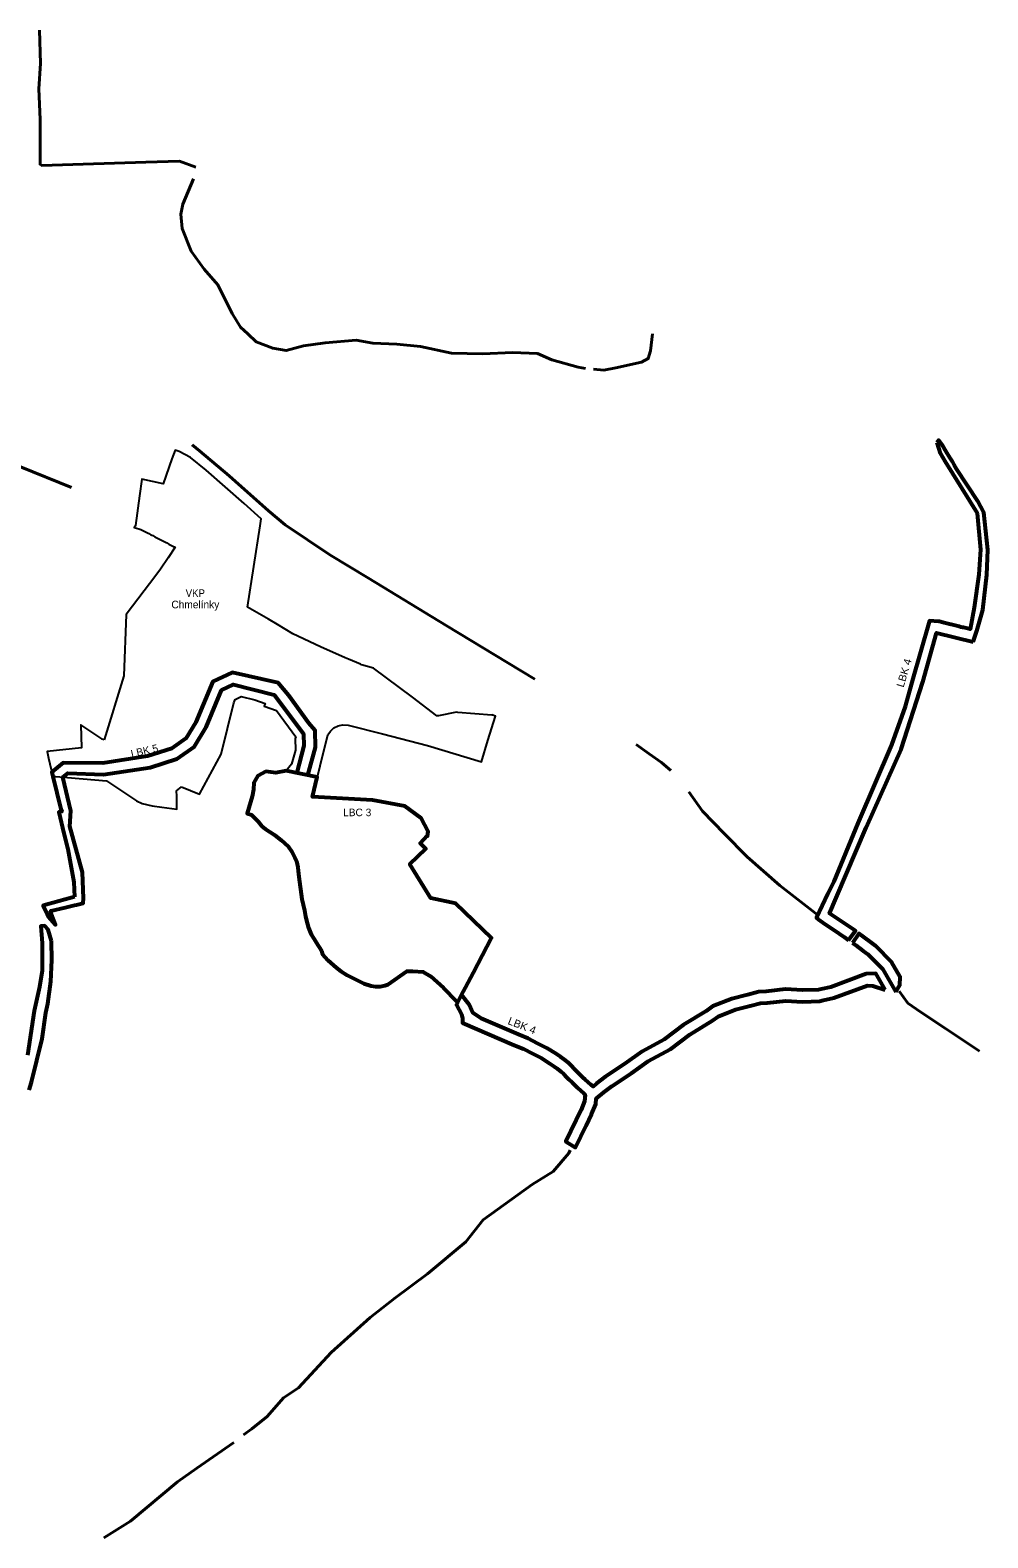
# Model space of a CAD drawing. Extents: x -555426 to -553015, y -1186745 to -1182687.
# Drawn here: x -554278 to -553015, y -1186745 to -1184759 of the extents above; entities that cross this region are included whole.
import ezdxf
from ezdxf.enums import TextEntityAlignment as Align

# ---------------------------------------------------------------- set-up
doc = ezdxf.new("R2010")
doc.units = 0
doc.header["$LTSCALE"] = 4
for name, color, linetype, lineweight in [('10', 7, 'Continuous', 25), ('12', 7, 'Continuous', 53), ('14', 7, 'Continuous', 53), ('51', 7, 'Continuous', 40)]:
    doc.layers.add(name, color=color, linetype=linetype, lineweight=lineweight)
doc.layers.add('13', color=7, linetype='Continuous')

msp = doc.modelspace()

# ---------------------------------------------------------------- linework, layer by layer
at = {"layer": '10'}
for points in [[(-553991.445, -1185519.302), (-553974.35, -1185411.9), (-553973.359, -1185402.641), (-553995.47, -1185382.52), (-554045.89, -1185338.45), (-554066.15, -1185321.95), (-554081.51, -1185313.86), (-554086.79, -1185312.33), (-554090.82, -1185323.71), (-554102.45, -1185356.48), (-554130.41, -1185350.705), (-554133.37, -1185372.6)], [(-554133.37, -1185372.6), (-554138.66, -1185411.73), (-554139.35, -1185412.26), (-554140.43, -1185414.36), (-554137.51, -1185415.07), (-554134.63, -1185415.78), (-554131.86, -1185416.61), (-554129.16, -1185417.97), (-554126.51, -1185419.33), (-554123.86, -1185420.72), (-554121.2, -1185422.09), (-554118.58, -1185423.63), (-554115.87, -1185424.86), (-554113.33, -1185426.32), (-554110.66, -1185427.61), (-554108, -1185428.97), (-554105.33, -1185430.33), (-554102.72, -1185431.7), (-554100.13, -1185433.15), (-554097.46, -1185434.4), (-554094.78, -1185435.91), (-554092.21, -1185437.3), (-554089.57, -1185438.64), (-554086.65, -1185440.17), (-554095.82, -1185454), (-554105.95, -1185469.05), (-554112.25, -1185477.32), (-554151.37, -1185528.59), (-554154.044, -1185609.726), (-554179.932, -1185693.741)], [(-553777.28, -1185857.816), (-553756.305, -1185837.627), (-553763.69, -1185830.09), (-553754.66, -1185819.8), (-553753.808, -1185820.661), (-553753.12, -1185814.47), (-553762.294, -1185797.04), (-553784.005, -1185781.139), (-553826.511, -1185773.188), (-553905.747, -1185768.755), (-553885.33, -1185687.443), (-553881.88, -1185682.283), (-553877.278, -1185678.216), (-553871.606, -1185675.434), (-553866.147, -1185674.256), (-553858.583, -1185674.394), (-553813.14, -1185685.807), (-553754.191, -1185701.479), (-553682.621, -1185722.715), (-553674.53, -1185694.64), (-553664.47, -1185662.51), (-553669.09, -1185660.85), (-553669.37, -1185661.4), (-553714.12, -1185657.64), (-553715.92, -1185657.49), (-553739.47, -1185662.06), (-553741.7, -1185662.44), (-553773.82, -1185637.86), (-553825.09, -1185599.26), (-553840.96, -1185594.97), (-553842.47, -1185594.31), (-553858.01, -1185587.49), (-553862.7, -1185585.67), (-553895.22, -1185571.18), (-553931.3, -1185554.25), (-553951.62, -1185541.91), (-553963.43, -1185534.75), (-553991.445, -1185519.302)], [(-554078.43, -1185755.55), (-554066.24, -1185760.67), (-554054.322, -1185765.455), (-554025.99, -1185712.685), (-554009.42, -1185645.24), (-554007.69, -1185640.76), (-553999.63, -1185636.97), (-553981.77, -1185641.17), (-553968.11, -1185645.82), (-553969.11, -1185649.61), (-553953.01, -1185655.12), (-553927.56, -1185690.05), (-553928.37, -1185692.13), (-553928.035, -1185707.442), (-553933.233, -1185725.789), (-553940.266, -1185734.657), (-553953.721, -1185737.409), (-553967.176, -1185735.575), (-553977.573, -1185741.079), (-553982.772, -1185750.559), (-553983.383, -1185759.121), (-553984.912, -1185768.295), (-553991.544, -1185790.708), (-553986.08, -1185792.84), (-553977.08, -1185801.46), (-553972.23, -1185807.6), (-553968.15, -1185811.02), (-553955.74, -1185819.21), (-553950.713, -1185822.993), (-553946.85, -1185825.9), (-553937.49, -1185834.57), (-553932.62, -1185841.17), (-553928.66, -1185848.69), (-553926.78, -1185853.53), (-553924.99, -1185861.78), (-553924.28, -1185866.6), (-553923.67, -1185874.2), (-553919.55, -1185903.59), (-553916.21, -1185918.48), (-553914.68, -1185926.61), (-553912.17, -1185936.62), (-553911.06, -1185941.63), (-553907.2, -1185950.33), (-553903.49, -1185956.33), (-553900.68, -1185960.74)], [(-554179.932, -1185693.741), (-554183.1, -1185693.05), (-554184.61, -1185691.85), (-554211.02, -1185674.13), (-554209.941, -1185704.245), (-554255.433, -1185709.182), (-554253.33, -1185718.22), (-554247.64, -1185742.08), (-554244.07, -1185742.37), (-554177.07, -1185747.73), (-554137.54, -1185774.16), (-554130.2, -1185777.76), (-554116.73, -1185780.93)], [(-554116.73, -1185780.93), (-554104.34, -1185782.34), (-554084.28, -1185785.25), (-554084.59, -1185768.1), (-554085.01, -1185761.01), (-554078.43, -1185755.55)], [(-553868.12, -1185998.62), (-553860.09, -1186003.76), (-553838.07, -1186014.61), (-553828.19, -1186017.87), (-553822.68, -1186018.8), (-553816.22, -1186018.59), (-553810.09, -1186017.51), (-553806.36, -1186016.14), (-553781.21, -1185998.52), (-553773.17, -1185998.47), (-553759.89, -1185999.41), (-553750.12, -1186005), (-553732.97, -1186020.51), (-553715.77, -1186037.98), (-553714.54, -1186040.11), (-553709.22, -1186029.91), (-553704, -1186019.94), (-553693.38, -1186000.29), (-553681.6, -1185977.59), (-553669.55, -1185954.79), (-553716.551, -1185909.351), (-553749.515, -1185902.394), (-553777.28, -1185857.816)], [(-553900.68, -1185960.74), (-553893.92, -1185971.59), (-553892.19, -1185976.11), (-553885.57, -1185984.25), (-553874.36, -1185993.93), (-553868.12, -1185998.62)]]:
    msp.add_lwpolyline(points, dxfattribs=at)
at = {"layer": '12'}
for points in [[(-553082.87, -1185302.3), (-553078.12, -1185316.33), (-553072.189, -1185326.659), (-553029.75, -1185395.3), (-553025.31, -1185442.94), (-553027.49, -1185476.25), (-553033.31, -1185519.72), (-553038.96, -1185548.27), (-553047.67, -1185546.08), (-553048.91, -1185545.77), (-553050.91, -1185545.27), (-553053.3, -1185544.68), (-553063.75, -1185542.07), (-553066.22, -1185541.44), (-553072.87, -1185539.73), (-553077.5, -1185538.57), (-553079.01, -1185538.14), (-553080.42, -1185537.9), (-553092.39, -1185537.23), (-553104.36, -1185578.25), (-553114.18, -1185613.7), (-553124.36, -1185649.89), (-553142.42, -1185700.66), (-553186.75, -1185803.57), (-553218.6, -1185880.58), (-553226.41, -1185896.66), (-553241.32, -1185928.48), (-553239.31, -1185930.03), (-553229.98, -1185936.55), (-553218.58, -1185944.24), (-553204.56, -1185953.8), (-553198.95, -1185957.78)], [(-553034.928, -1185564.727), (-553030.13, -1185550.39), (-553022.24, -1185522.46), (-553016.78, -1185476.64), (-553015.45, -1185443.7), (-553020.83, -1185394.62), (-553028.51, -1185379.69), (-553056.68, -1185336.83), (-553059.75, -1185331.58), (-553062.27, -1185327.43), (-553065.55, -1185322), (-553070.46, -1185313.92), (-553074.85, -1185306.8), (-553080.44, -1185299.18), (-553082.87, -1185302.3)], [(-553198.95, -1185957.78), (-553190.044, -1185945.316), (-553224.037, -1185922.537), (-553215.31, -1185901.96), (-553175.94, -1185809.23), (-553129.62, -1185706.16), (-553101.04, -1185617.53), (-553083.083, -1185552.819), (-553034.928, -1185564.727)], [(-553911.701, -1185740.404), (-553901.745, -1185703.425), (-553902.205, -1185681.771), (-553910.4, -1185671.8), (-553936.71, -1185635.55), (-553950.94, -1185618.77), (-554011.334, -1185605.071), (-554036.928, -1185617.149), (-554059.19, -1185670.456), (-554072.415, -1185692.214), (-554090.982, -1185705.416), (-554123.033, -1185715.514), (-554181.927, -1185724.575), (-554233.989, -1185724.118), (-554248.948, -1185736.596), (-554247.64, -1185742.08), (-554237.39, -1185785.09), (-554235.75, -1185788.44), (-554240.03, -1185789.13), (-554233.38, -1185817.23), (-554228.1, -1185837.77), (-554220.03, -1185881.16), (-554219.04, -1185900.71)], [(-554219.04, -1185900.71), (-554260.557, -1185912.173), (-554256.71, -1185920.61), (-554254.1, -1185926.61), (-554244.35, -1185937.42), (-554249.57, -1185923.77), (-554250.31, -1185919.09), (-554231.43, -1185914.6), (-554219.41, -1185911.75), (-554216.82, -1185911.13), (-554207.981, -1185909.04), (-554207.51, -1185902.62), (-554208.92, -1185868.43), (-554225.516, -1185808.235), (-554224.11, -1185787.364), (-554234.745, -1185743.116), (-554228.051, -1185737.626), (-554180.845, -1185739.585), (-554119.619, -1185730.166), (-554084.218, -1185719.012), (-554061.203, -1185702.646), (-554045.784, -1185677.28), (-554025.31, -1185628.253), (-554009.786, -1185620.927), (-553956.216, -1185634.769), (-553917.292, -1185685.82), (-553916.787, -1185701.599), (-553926.437, -1185737.439)], [(-554249.398, -1185958.956), (-554253.834, -1185943.99), (-554258.932, -1185938.814), (-554263.54, -1185939.09), (-554261.93, -1185961.69), (-554261.867, -1185997.814), (-554265.332, -1186019.412), (-554272.29, -1186050.65), (-554281.22, -1186109.23)], [(-554278.86, -1186154.79), (-554275.9, -1186144.9), (-554261.77, -1186087.91), (-554257.23, -1186053.46), (-554254.24, -1186041.58), (-554250.48, -1186012.28), (-554249.25, -1185984.3), (-554249.398, -1185958.956)], [(-553136.76, -1186025.81), (-553131.636, -1186017.15), (-553130.875, -1186005.959), (-553141.815, -1185986.942), (-553163.584, -1185965.017), (-553170.649, -1185959.736), (-553185.396, -1185948.905), (-553193.99, -1185961.2)], [(-553193.99, -1185961.2), (-553189.33, -1185964.5), (-553179.63, -1185971.75), (-553173.45, -1185976.37), (-553153.84, -1185996.12), (-553136.76, -1186025.81)], [(-553150.76, -1186023.24), (-553162.91, -1186001.77), (-553175.828, -1186001.958), (-553222.523, -1186019.488), (-553235.037, -1186022.23), (-553238.873, -1186023.052), (-553259.583, -1186023.736), (-553282.021, -1186022.434), (-553307.71, -1186025.165), (-553317.736, -1186025.993), (-553332.406, -1186029.69), (-553352.717, -1186034.988), (-553378.046, -1186044.879), (-553386.83, -1186051.112), (-553416.569, -1186069.411), (-553442.07, -1186088.791), (-553471.261, -1186104.366), (-553493.836, -1186120.687), (-553519.846, -1186137.769), (-553531.202, -1186146.372), (-553535.863, -1186150.358), (-553538.103, -1186148.406), (-553546.022, -1186141.348), (-553548.683, -1186138.882), (-553553.043, -1186134.503), (-553557.145, -1186130.6), (-553560.554, -1186127.153), (-553563.838, -1186123.82), (-553568.263, -1186119.334), (-553574.069, -1186114.956), (-553578.7, -1186111.427), (-553584.623, -1186107.599), (-553596.515, -1186099.928), (-553608.823, -1186093.668), (-553621.239, -1186087.362), (-553633.865, -1186082.054), (-553683.475, -1186060.759), (-553694.198, -1186053.632), (-553699.051, -1186042.658), (-553709.22, -1186029.91)], [(-553714.54, -1186040.11), (-553715.99, -1186043.02), (-553709.24, -1186055.23), (-553707.92, -1186060.73), (-553707.78, -1186066.65), (-553639.73, -1186095.86), (-553627.55, -1186100.98), (-553615.62, -1186107.04), (-553604, -1186112.95), (-553592.76, -1186120.2), (-553587.33, -1186123.71), (-553583.13, -1186126.91), (-553578.17, -1186130.65), (-553574.52, -1186134.35), (-553571.23, -1186137.69), (-553567.65, -1186141.31), (-553563.53, -1186145.23), (-553559.1, -1186149.68), (-553556.11, -1186152.45), (-553548.02, -1186159.66), (-553546.182, -1186161.261), (-553546.991, -1186169.987), (-553551.543, -1186181.231), (-553571.668, -1186222.815), (-553558.79, -1186230.64), (-553551.72, -1186216.33), (-553544.71, -1186202.05), (-553537.64, -1186186.86), (-553532.26, -1186173.57), (-553531.6, -1186166.45), (-553521.79, -1186158.06), (-553511.19, -1186150.03), (-553485.32, -1186133.04), (-553463.3, -1186117.12), (-553433.95, -1186101.46), (-553408.08, -1186081.8), (-553378.55, -1186063.63), (-553370.87, -1186058.18), (-553348.08, -1186049.28), (-553328.68, -1186044.22), (-553315.27, -1186040.84), (-553306.3, -1186040.1), (-553281.66, -1186037.48), (-553259.77, -1186038.75), (-553237.04, -1186038), (-553231.86, -1186036.89), (-553218.26, -1186033.91), (-553173.99, -1186017.29), (-553167.22, -1186018.11), (-553150.76, -1186023.24)]]:
    msp.add_lwpolyline(points, dxfattribs=at)
at = {"layer": '14'}
msp.add_lwpolyline([(-553940.266, -1185734.657), (-553953.721, -1185737.409), (-553967.176, -1185735.575), (-553977.573, -1185741.079), (-553982.772, -1185750.559), (-553983.383, -1185759.121), (-553984.912, -1185768.295), (-553991.544, -1185790.708), (-553986.08, -1185792.84), (-553977.08, -1185801.46), (-553972.23, -1185807.6), (-553968.15, -1185811.02), (-553955.74, -1185819.21), (-553950.713, -1185822.993), (-553946.85, -1185825.9), (-553937.49, -1185834.57), (-553932.62, -1185841.17), (-553928.66, -1185848.69), (-553926.78, -1185853.53), (-553924.99, -1185861.78), (-553924.28, -1185866.6), (-553923.67, -1185874.2), (-553919.55, -1185903.59), (-553916.21, -1185918.48), (-553914.68, -1185926.61), (-553912.17, -1185936.62), (-553911.06, -1185941.63), (-553907.2, -1185950.33), (-553903.49, -1185956.33), (-553900.68, -1185960.74), (-553893.92, -1185971.59), (-553892.19, -1185976.11), (-553885.57, -1185984.25), (-553874.36, -1185993.93), (-553868.12, -1185998.62), (-553860.09, -1186003.76), (-553838.07, -1186014.61), (-553828.19, -1186017.87), (-553822.68, -1186018.8), (-553816.22, -1186018.59), (-553810.09, -1186017.51), (-553806.36, -1186016.14), (-553781.21, -1185998.52), (-553773.17, -1185998.47), (-553759.89, -1185999.41), (-553750.12, -1186005), (-553732.97, -1186020.51), (-553715.77, -1186037.98), (-553714.54, -1186040.11), (-553709.22, -1186029.91), (-553704, -1186019.94), (-553693.38, -1186000.29), (-553681.6, -1185977.59), (-553669.55, -1185954.79), (-553716.551, -1185909.351), (-553749.515, -1185902.394), (-553777.28, -1185857.816), (-553756.305, -1185837.627), (-553763.69, -1185830.09), (-553754.66, -1185819.8), (-553753.808, -1185820.661), (-553753.12, -1185814.47), (-553762.294, -1185797.04), (-553784.005, -1185781.139), (-553826.511, -1185773.188), (-553905.747, -1185768.755), (-553899.257, -1185742.908)], close=True, dxfattribs=at)
at = {"layer": '51'}
msp.add_line((-554290.423, -1185334.268), (-554223.316, -1185361.296), dxfattribs=at)
for points in [[(-554265.597, -1184759.064), (-554264.211, -1184803.186), (-554266.06, -1184836.335), (-554264.673, -1184876.761), (-554264.327, -1184917.765), (-554264.558, -1184935.668), (-554262.133, -1184937.285), (-554207.962, -1184935.783), (-554125.149, -1184933.01), (-554080.912, -1184931.623), (-554059.313, -1184939.362)], [(-554062.316, -1184955.07), (-554076.408, -1184988.45), (-554079.18, -1185001.502), (-554077.216, -1185020.328), (-554065.435, -1185050.012), (-554048.341, -1185074.037), (-554030.324, -1185094.596), (-554011.497, -1185132.134), (-554000.409, -1185150.153), (-553990.707, -1185159.277), (-553979.849, -1185169.557), (-553958.02, -1185178.104), (-553940.348, -1185181.107), (-553917.247, -1185174.986), (-553889.065, -1185170.943), (-553848.178, -1185167.593), (-553826.118, -1185171.173), (-553794.586, -1185172.675), (-553763.4, -1185175.678), (-553722.283, -1185184.34), (-553680.933, -1185185.379), (-553642.009, -1185183.647), (-553609.091, -1185185.148), (-553589.917, -1185193.233), (-553555.267, -1185203.051), (-553545.665, -1185204.918)], [(-553535.401, -1185205.823), (-553521.54, -1185206.863), (-553505.948, -1185203.86), (-553471.874, -1185196.584), (-553462.981, -1185191.733), (-553460.093, -1185181.568), (-553457.437, -1185159.276)], [(-554064.038, -1185305.277), (-554054.336, -1185313.016), (-554015.296, -1185345.934), (-553963.667, -1185392.018), (-553941.606, -1185410.729), (-553882.932, -1185450.115), (-553831.88, -1185481.07), (-553729.314, -1185543.093), (-553648.002, -1185592.297), (-553612.585, -1185614.075)], [(-553478.794, -1185700.061), (-553461.699, -1185712.42), (-553445.645, -1185723.508), (-553433.401, -1185734.249)], [(-553409.609, -1185762.547), (-553391.36, -1185787.611), (-553363.178, -1185817.411), (-553332.801, -1185848.019), (-553289.604, -1185885.558), (-553238.215, -1185925.514)], [(-553132.496, -1186024.883), (-553120.811, -1186040.878), (-553103.948, -1186052.429), (-553071.261, -1186074.028), (-553026.678, -1186104.057)], [(-553996.367, -1186609.522), (-553985.51, -1186601.437), (-553965.182, -1186585.382), (-553943.814, -1186560.78), (-553924.063, -1186547.266), (-553881.096, -1186500.949), (-553829.527, -1186454.632), (-553797.186, -1186429.221), (-553754.161, -1186397.111), (-553703.572, -1186355.069), (-553680.703, -1186326.309), (-553615.906, -1186279.529), (-553588.3, -1186262.665), (-553567.856, -1186238.178), (-553566.128, -1186234.526)], [(-554180.651, -1186745.008), (-554145.308, -1186722.831), (-554083.63, -1186671.317), (-554057.815, -1186653.183), (-554009.073, -1186619.455)]]:
    msp.add_lwpolyline(points, dxfattribs=at)

# ---------------------------------------------------------------- texts
at = {"layer": '10', "width": 0.95}
msp.add_text('VKP', height=10, dxfattribs=at).set_placement((-554060.005, -1185505.615), align=Align.CENTER)
at = {"layer": '10'}
msp.add_text('Chmelínky', height=10, dxfattribs=at).set_placement((-554060.005, -1185520.615), align=Align.CENTER)
at = {"layer": '13', "width": 1.05}
for rotation, p in [(73.3, (-553121.117, -1185607.17)), (338.743, (-553631.19, -1186074.901))]:
    msp.add_text('LBK 4', height=10, rotation=rotation, dxfattribs=at).set_placement(p, align=Align.CENTER)
at = {"layer": '13'}
msp.add_text('LBK 5', height=10, rotation=12.969, dxfattribs=at).set_placement((-554125.954, -1185713.296), align=Align.CENTER)
msp.add_text('LBC 3', height=10, dxfattribs=at).set_placement((-553846.648, -1185794.45), align=Align.CENTER)

doc.saveas('drawing.dxf')
